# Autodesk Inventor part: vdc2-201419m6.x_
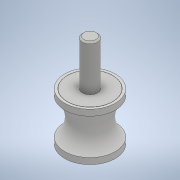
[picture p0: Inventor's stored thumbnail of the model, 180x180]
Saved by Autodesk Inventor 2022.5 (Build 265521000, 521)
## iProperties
Created: 2018-04
Part Number: vdc2-201419m6.x_
Material: 一般
Document SubType Name: Modeling
Designer: imaocorp
Density: 1 g/cm^3
Appearance: 既定
Sending System: SOLIDWORKS 2016-2016286
MC: AMD64
MC_MODEL: AMD64 Family 21 Model 2 Stepping 0, AuthenticAMD
OS: Windows_NT
FRU: Parasolid Version 28.0, build 224,  7-29-2016
FORMAT: text
GUISE: transmit
KEY: vdc2-201419m6
FILE: vdc2-201419m6.x_t
DATE: Wed Apr 25 10:15:17 2018
Author: imaocorp
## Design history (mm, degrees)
feature "Base1"
node "ソリッド1"
